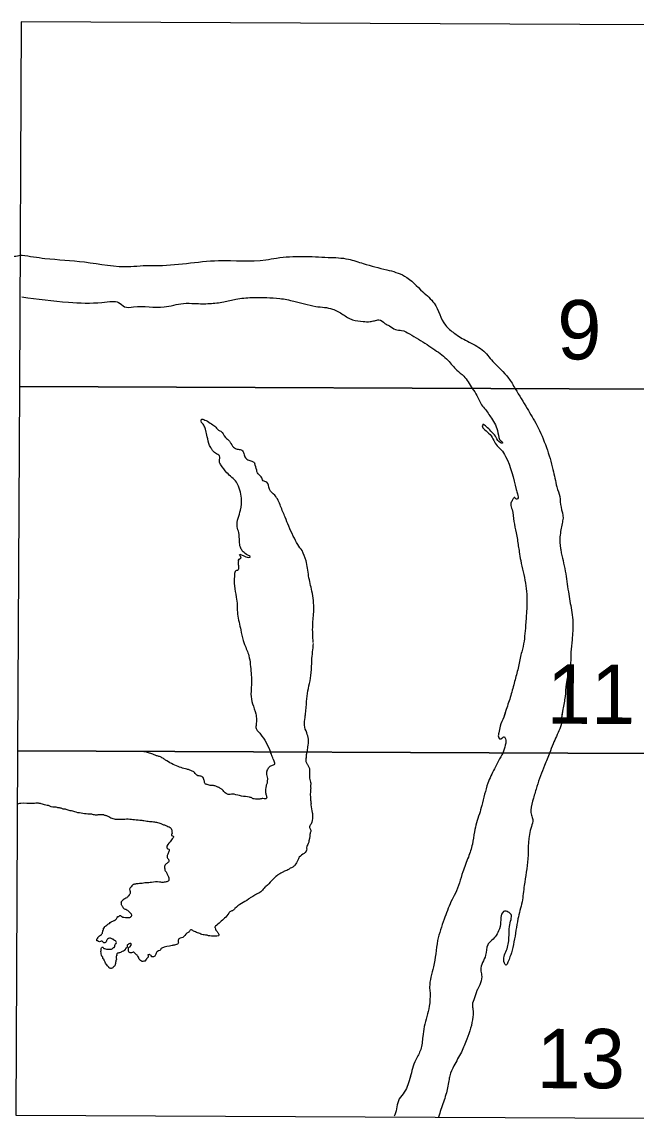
# Model space of a CAD drawing. Extents: x 3161564 to 3199464, y 849354 to 874788.
# Drawn here: x 3187465 to 3188676, y 851608 to 853769 of the extents above; entities that cross this region are included whole.
import ezdxf

# ---------------------------------------------------------------- set-up
doc = ezdxf.new("R2010")
doc.units = 0
doc.layers.add('V-ANNO-NPLT', color=7, linetype='Continuous')

msp = doc.modelspace()

# ---------------------------------------------------------------- linework, layer by layer
at = {"layer": 'V-ANNO-NPLT'}
for p, q in [((3188418, 852407.9), (3188415, 852398.6)), ((3188530.4, 852407.6), (3188529.1, 852396.2))]:
    msp.add_line(p, q, dxfattribs=at)
for points in [[(3187460.3, 853050.6), (3188699.2, 853044.8), (3188702.3, 853763.2), (3187464, 853769), (3187460.3, 853050.6)], [(3187456.7, 852332.3), (3188696.2, 852326.5), (3188699.2, 853044.8), (3187460.3, 853050.6), (3187456.7, 852332.3)], [(3187453, 851613.9), (3188693.2, 851608.1), (3188696.2, 852326.5), (3187456.7, 852332.3), (3187453, 851613.9)]]:
    msp.add_lwpolyline(points, dxfattribs=at)
for points in [[(3187329.4, 853339.6), (3187342.8, 853337.5), (3187357.1, 853333.9), (3187373.6, 853330.3), (3187388.4, 853326.6), (3187398.2, 853323), (3187410, 853319.9), (3187421.8, 853316.2), (3187431, 853312.6), (3187436.7, 853309.5), (3187442.8, 853306.9), (3187453.1, 853307.4), (3187465.5, 853309.5)], [(3187465.5, 853309.5), (3187510.7, 853302.9), (3187588.5, 853295.8), (3187680, 853286.9), (3187704.2, 853288.6), (3187726.7, 853288.5), (3187852.9, 853298.5), (3187946.2, 853300), (3187967, 853303.4), (3188018.8, 853306.7), (3188068.9, 853304.9), (3188108.7, 853301.3), (3188138, 853292.6), (3188184.6, 853280.3), (3188219.2, 853268.1), (3188255.4, 853236.9), (3188277.8, 853214.3), (3188300.1, 853171), (3188317.4, 853155.4), (3188343.2, 853139.7), (3188372.6, 853122.4), (3188393.3, 853099.8), (3188424.3, 853066.9), (3188437.6, 853045.8)], [(3187465.3, 853226.8), (3187557.1, 853216.3), (3187622.8, 853216.1), (3187643.5, 853217.8), (3187655.6, 853216), (3187667.7, 853207.4), (3187685, 853207.3), (3187745.5, 853207.1), (3187783.5, 853214), (3187806, 853213.9), (3187835.4, 853213.8), (3187863, 853217.2), (3187887.2, 853222.3), (3187918.3, 853225.7), (3187947.7, 853225.6), (3187973.6, 853223.8), (3188001.3, 853218.5), (3188022, 853213.3), (3188044.5, 853208), (3188061.7, 853206.3), (3188077.3, 853202.8), (3188098, 853192.3), (3188117, 853181.9), (3188137.7, 853178.4), (3188151.5, 853178.3), (3188160.2, 853180), (3188168.8, 853181.8), (3188180.9, 853174.8), (3188189.5, 853169.6), (3188201.6, 853162.6), (3188213.7, 853160.9), (3188229.2, 853153.9), (3188263.7, 853133), (3188279.3, 853122.6), (3188305.1, 853101.8), (3188322.3, 853082.7), (3188336.1, 853070.6), (3188352.6, 853046.6)], [(3188352.8, 853046.3), (3188362.2, 853032.4), (3188369.6, 853016.7), (3188377.1, 853007.1), (3188390.7, 852987.9), (3188403.6, 852959.2), (3188409.7, 852942.8), (3188411.8, 852941.4), (3188412.4, 852938.6), (3188408.3, 852939.3), (3188400.2, 852949.6), (3188392, 852959.9), (3188383.2, 852968.8), (3188377, 852974.3), (3188374.3, 852975.7), (3188373.6, 852975), (3188385.2, 852958.5), (3188400.1, 852935.9), (3188409.7, 852925.7), (3188418.5, 852912.6), (3188439.5, 852847)], [(3188437.6, 853045.9), (3188461.1, 853006.9), (3188480.1, 852974), (3188499.1, 852930.2), (3188512, 852886.4), (3188519.4, 852852.2)], [(3187827, 852966.3), (3187823.7, 852974), (3187818.5, 852981.8), (3187818.5, 852984.4), (3187819.8, 852985.7), (3187823.7, 852985), (3187828.2, 852983.1), (3187839.2, 852976.5), (3187847.6, 852970), (3187852.8, 852964.2), (3187857.3, 852962.2), (3187866.4, 852949.9), (3187874.1, 852942.7), (3187877.3, 852937.6), (3187884.4, 852929.1), (3187891.5, 852926.5), (3187898.7, 852924.5), (3187902.5, 852918), (3187903.8, 852913.5), (3187905.7, 852909.6), (3187912.8, 852905), (3187920, 852902.4), (3187922.5, 852901.1), (3187924.2, 852898.2)], [(3187857.5, 852895.8), (3187854.6, 852902), (3187855.2, 852908.4), (3187854.6, 852913.6), (3187846.8, 852918.8), (3187839.7, 852926.6), (3187835.2, 852933.8), (3187830.7, 852951.3), (3187827.5, 852963.6), (3187827, 852966.3)], [(3187891.9, 852705.8), (3187893.2, 852709.7), (3187897.1, 852712.2), (3187893.9, 852718.7), (3187906.8, 852714.8), (3187911.3, 852713.5), (3187915.2, 852714.1), (3187908.1, 852719.3), (3187899.7, 852726.5), (3187895.9, 852733.6), (3187894, 852745.3), (3187892.7, 852762.2), (3187889.5, 852773.8), (3187891.5, 852790.7), (3187896.1, 852806.2), (3187898.1, 852830.2), (3187894.9, 852845.8), (3187888.4, 852861.4), (3187869.1, 852880.2), (3187857.5, 852895.8)], [(3188017.6, 852726.8), (3188009.2, 852738.5), (3188000.2, 852755.4), (3187991.2, 852774.9), (3187984.1, 852792.4), (3187975.1, 852814.4), (3187963.5, 852835.9), (3187953.2, 852847.6), (3187948, 852861.8), (3187940.9, 852864.5), (3187937, 852872.2), (3187929.3, 852880), (3187928, 852885.2), (3187924.2, 852898.2)], [(3188519.4, 852852.2), (3188525.2, 852833.4), (3188527.8, 852812.2), (3188531.9, 852791), (3188529.8, 852780.1), (3188527.7, 852767.8), (3188525.6, 852754.1), (3188526.9, 852730.8), (3188528.3, 852722.6)], [(3188439.5, 852847), (3188441.9, 852838.4), (3188441.8, 852828.8), (3188439.8, 852828.2), (3188435.7, 852831.6), (3188435, 852830.9), (3188431.6, 852825.4), (3188428.8, 852818.6), (3188431.5, 852807.7), (3188434.9, 852784.4), (3188439.6, 852761.8), (3188443.6, 852735.9), (3188445.6, 852724.2)], [(3188039.4, 852545.9), (3188038.5, 852579.6), (3188040.6, 852609.4), (3188036.8, 852647), (3188030.4, 852676.9), (3188025.3, 852706.7), (3188017.6, 852726.8)], [(3188445.6, 852724.2), (3188448.3, 852707.1), (3188457.8, 852662.7), (3188460.4, 852640.8), (3188459.6, 852602.5), (3188457.5, 852573.8), (3188451.9, 852532.8), (3188448.5, 852521.2)], [(3188528.3, 852722.6), (3188537, 852680.9), (3188543.1, 852640.6), (3188549.1, 852605), (3188551.1, 852585.2), (3188549.6, 852551), (3188547.5, 852526.4)], [(3187891.9, 852706.4), (3187891.9, 852697.4), (3187891.9, 852690.9), (3187889.9, 852687.6), (3187886.7, 852687), (3187884.7, 852683.8), (3187884, 852676), (3187884, 852657.2), (3187887.8, 852635.1), (3187889.7, 852618.9), (3187889.7, 852611.2), (3187890.3, 852601.4), (3187896.7, 852570.3), (3187901.2, 852549.5), (3187904.1, 852541.6)], [(3187904.1, 852541.6), (3187912.4, 852519.6), (3187916.9, 852485.2), (3187918.1, 852469), (3187916.7, 852443.7), (3187919.9, 852424.9), (3187926.3, 852404.8), (3187927.6, 852393.8), (3187926.9, 852384), (3187926.9, 852376.3), (3187930.1, 852371.1), (3187935.3, 852365.2), (3187955.5, 852329.9)], [(3188027.4, 852329.6), (3188029.1, 852339.7), (3188029.8, 852355.2), (3188026.6, 852367.6), (3188022.1, 852382.5), (3188023.5, 852398), (3188026.1, 852424), (3188028.1, 852445.3), (3188032.1, 852464.8), (3188035.3, 852486.2), (3188036.7, 852510.1), (3188040, 852543.8)], [(3188448.5, 852521.2), (3188443.3, 852494.9), (3188436.4, 852468.9), (3188428.8, 852440.9), (3188419.9, 852413.6), (3188415, 852398.6)], [(3188547.5, 852526.4), (3188545.1, 852493.9), (3188538.1, 852463.8), (3188536, 852439.2), (3188531.2, 852414), (3188529.1, 852396.2)], [(3187924.9, 852409.3), (3187926.3, 852404.8), (3187927.6, 852393.8), (3187926.9, 852384), (3187926.9, 852376.3), (3187930.1, 852371.1), (3187935.3, 852365.2), (3187955.5, 852329.9)], [(3188027.4, 852329.6), (3188029.1, 852339.7), (3188029.8, 852355.2), (3188026.6, 852367.6), (3188022.1, 852382.5), (3188023.4, 852398), (3188024.6, 852409)], [(3188415, 852398.6), (3188407.8, 852380.5), (3188405.1, 852367.5), (3188404.3, 852360), (3188406.4, 852355.9), (3188412.5, 852357.9), (3188415.3, 852359.9), (3188418.7, 852355.8), (3188419.3, 852351), (3188418, 852343.5), (3188413.1, 852327.8)], [(3188415, 852398.6), (3188407.8, 852380.5), (3188405, 852367.5), (3188404.3, 852360), (3188406.4, 852355.8), (3188412.5, 852357.9), (3188415.3, 852359.9), (3188418.7, 852355.8), (3188419.3, 852351), (3188418, 852343.5), (3188413.1, 852327.8)], [(3188529.2, 852397), (3188528, 852383.5), (3188525.3, 852375.4), (3188512.2, 852346), (3188505.3, 852327.6)], [(3188529.2, 852397), (3188528, 852383.5), (3188525.3, 852375.3), (3188512.2, 852346), (3188505.3, 852327.5)], [(3187850.3, 852260.9), (3187844, 852263.4), (3187841.4, 852263.9), (3187838.3, 852263.8), (3187830.7, 852265.4), (3187828.3, 852266.1), (3187826.6, 852267.1), (3187824.9, 852272.1), (3187823.9, 852275.7), (3187822.5, 852279.3), (3187821.2, 852280.4), (3187818.2, 852282.1), (3187811.8, 852283), (3187805.4, 852289.3), (3187799.5, 852292.8), (3187793.4, 852295.1), (3187790.5, 852295.9), (3187784.7, 852297.3), (3187773.1, 852300.9), (3187760.1, 852307), (3187748.1, 852314), (3187742.7, 852317.7), (3187736.6, 852320.7), (3187730.4, 852322.5), (3187721.2, 852326.3), (3187712.6, 852328.9), (3187703, 852331), (3187702.7, 852331.1)], [(3188025.6, 852318.2), (3188024.6, 852314.2), (3188026, 852308.3), (3188029, 852303.9), (3188029.9, 852301.3), (3188031.2, 852298.9), (3188032.3, 852291.4), (3188032.2, 852280.7), (3188032.6, 852275.6), (3188034.7, 852265.7), (3188033.9, 852263), (3188034.3, 852260.6), (3188034.4, 852258), (3188033.9, 852255.4), (3188034.3, 852252.7), (3188033.2, 852247.3), (3188034.1, 852242.1), (3188033.8, 852239.5), (3188033.9, 852236.7), (3188035.1, 852228.4), (3188034.9, 852225.7), (3188037.6, 852210.2), (3188037.7, 852202.3), (3188035.4, 852188), (3188033.5, 852185.6), (3188032.1, 852182.5), (3188034, 852177.3), (3188034.6, 852174.6), (3188034.3, 852171.8), (3188033.1, 852168.8), (3188032.5, 852166), (3188032.6, 852163.2), (3188032.2, 852160.4), (3188031.5, 852157.6), (3188031.1, 852155), (3188029.6, 852149.6), (3188026.3, 852141.2), (3188026.6, 852138.8), (3188012, 852122.2), (3188010.2, 852119.4), (3188009, 852116.3), (3188003.2, 852106.8), (3187999, 852102.9), (3187994.1, 852100.5), (3187991.9, 852098.8), (3187987.2, 852096.4), (3187983, 852095), (3187980.6, 852093.4), (3187978.1, 852092.2), (3187973.5, 852089.7), (3187968.7, 852086.5), (3187946.3, 852064.9), (3187944.2, 852063.1), (3187938, 852055.9), (3187930.2, 852050.7), (3187925.6, 852048.3), (3187918.8, 852044), (3187913.9, 852041.3), (3187911.6, 852039.5), (3187885.1, 852021.2), (3187880.7, 852017), (3187877.8, 852016.1), (3187875, 852014.6), (3187873.1, 852012.1), (3187864.6, 852002), (3187846.8, 851986.4), (3187845.5, 851984.5), (3187845.9, 851983), (3187847.8, 851978.3), (3187851.6, 851973.7), (3187852.6, 851971.4), (3187854.2, 851969.2), (3187852.5, 851967.6), (3187846.9, 851966.7), (3187838.7, 851966.8), (3187833.2, 851967.6), (3187830.2, 851968.4), (3187827.3, 851969), (3187822.2, 851969.5), (3187813.7, 851972.9), (3187805.3, 851975.9), (3187802.3, 851977.8), (3187799.5, 851979.1), (3187797, 851978.6), (3187795.1, 851975.9), (3187793, 851974), (3187790.6, 851972.5), (3187782.2, 851964.3), (3187777.2, 851963), (3187773.3, 851958.5), (3187773, 851955.8), (3187773.6, 851953.5), (3187771.6, 851950.9), (3187764.2, 851948.8), (3187761.6, 851948.2), (3187741, 851943), (3187738.9, 851941.5)], [(3187948.7, 852293.2), (3187952.7, 852300.1), (3187954.7, 852301.9), (3187961, 852304.4), (3187963.5, 852306), (3187961.5, 852313.6), (3187960.8, 852315.9), (3187958.6, 852320.8), (3187955.5, 852329.9)], [(3188025.6, 852318.2), (3188026.1, 852320.8), (3188026.2, 852323.4), (3188027.4, 852329.6)], [(3188413.1, 852327.8), (3188396.5, 852296.6), (3188383.7, 852268.2), (3188371.8, 852224.3), (3188366.9, 852207.6), (3188357, 852172.5), (3188353.1, 852148), (3188345.2, 852122.6), (3188334.4, 852093.3), (3188319.6, 852051.3), (3188310.7, 852034.7)], [(3188505.7, 852328.6), (3188495.1, 852303.1), (3188480.4, 852262.1), (3188473.5, 852238.6), (3188468.5, 852215.2), (3188469.5, 852205.4), (3188472.4, 852196.6), (3188469.4, 852182.9), (3188462.4, 852119.4), (3188455.4, 852066.6), (3188451.4, 852034.3)], [(3187948.7, 852293.3), (3187947.3, 852290.3), (3187947.4, 852285.2), (3187949.1, 852275.2), (3187948.8, 852272.6), (3187948.9, 852270.1), (3187946.6, 852264.4), (3187946.5, 852261.9), (3187946, 852259.1), (3187945.3, 852253.8), (3187946.3, 852246.4), (3187947.9, 852239.9), (3187947.9, 852239.3), (3187947, 852238), (3187945.6, 852237.4), (3187940.3, 852238), (3187937.2, 852237.5), (3187935.8, 852237.2), (3187928, 852236.8), (3187922.9, 852237.2), (3187916.8, 852239.8), (3187914.1, 852240.6), (3187897.9, 852242.9), (3187883.5, 852246.4), (3187878.3, 852246.7), (3187873.3, 852246), (3187870.5, 852246.6), (3187867.7, 852248), (3187861.9, 852253.6), (3187861.4, 852254.5), (3187858.9, 852256.4), (3187854.2, 852259.5), (3187851.9, 852260.6), (3187850.3, 852260.9)], [(3187626.8, 852205.7), (3187623.7, 852205.9), (3187615.2, 852205.7), (3187612.6, 852205.5), (3187604.3, 852206.7), (3187601.5, 852207.5), (3187598.9, 852207.3), (3187585.3, 852208.8), (3187572, 852211), (3187563.2, 852213.8), (3187560.6, 852213.8), (3187552.2, 852216.7), (3187549.5, 852217), (3187543.9, 852218.2), (3187540.9, 852219.3), (3187538, 852219.6), (3187531.4, 852221.1), (3187528.8, 852220.9), (3187517.6, 852224), (3187512.1, 852225.1), (3187503.5, 852227.8), (3187500.6, 852228.3), (3187497.9, 852228.6), (3187492.5, 852228.6), (3187487.2, 852228.1), (3187463.1, 852228.5), (3187460.5, 852228.1), (3187456.1, 852226.9)], [(3187626.8, 852205.7), (3187629.5, 852205.3), (3187632.2, 852204.4), (3187640.8, 852200.2), (3187648.9, 852197.7), (3187664.9, 852197.4), (3187678.2, 852197.6), (3187683.8, 852196.8), (3187697.5, 852195.7), (3187705.8, 852194.5), (3187711.5, 852193.6), (3187722.3, 852192.6), (3187730.4, 852191.4), (3187739.1, 852188.9), (3187744.6, 852186.4), (3187747.6, 852185.5), (3187750.6, 852184.2), (3187759.3, 852178.9), (3187761, 852171.8), (3187761.1, 852169.2), (3187760, 852166.4), (3187760.4, 852165.4), (3187763.4, 852164), (3187764.2, 852162.6), (3187763.2, 852160.9), (3187757.3, 852152.7), (3187751, 852141.1), (3187751.8, 852139.4), (3187754.7, 852138.3), (3187755.6, 852137.2), (3187755.6, 852135.1), (3187753, 852128.7), (3187751.8, 852125.6), (3187751.4, 852122.9), (3187752.4, 852120.5), (3187754.3, 852118.1), (3187755, 852115.7), (3187753.9, 852112.9), (3187751.8, 852110.7), (3187749.4, 852109.1), (3187747.3, 852107.1), (3187746.6, 852104.4), (3187746.6, 852101.7), (3187747.2, 852096.9), (3187750.1, 852092.4), (3187751.2, 852090), (3187753.3, 852085.3), (3187755.1, 852077.8), (3187754.8, 852076.2), (3187753.3, 852075), (3187751.2, 852074.1), (3187743.9, 852072.8), (3187738.8, 852073), (3187736.2, 852073.5), (3187720.5, 852072.8), (3187715.4, 852072), (3187704.8, 852071.3), (3187699.7, 852070.4), (3187694.6, 852070.2), (3187686.9, 852069.1), (3187684.4, 852068.5), (3187683.6, 852067.9), (3187680.8, 852064.1), (3187678.8, 852062), (3187677.6, 852059.2), (3187678.6, 852054.7), (3187678.8, 852052.2), (3187677.7, 852049.4), (3187675.9, 852046.5), (3187673.9, 852044.3), (3187671.8, 852042.6), (3187665, 852038.6), (3187661.7, 852034.9)], [(3187647.7, 851945.9), (3187648.4, 851946.6), (3187648.9, 851950.4), (3187651.1, 851952.4), (3187650.5, 851956.6), (3187649.8, 851957.4), (3187646.1, 851959.6), (3187644.8, 851960.9), (3187643.5, 851961.1), (3187641.1, 851962.4), (3187638.2, 851962.8), (3187633.8, 851961), (3187632.6, 851958.9), (3187631.9, 851957.6), (3187630.3, 851954.3), (3187626.9, 851953.5), (3187624.8, 851955.5), (3187621.7, 851957.1), (3187618, 851955.9), (3187616.1, 851956.5), (3187614.6, 851957.4), (3187613.8, 851957.5), (3187613.1, 851957.7), (3187612.8, 851960), (3187613.1, 851961.2), (3187614.3, 851962.3), (3187615, 851963.9), (3187621.9, 851970), (3187624.5, 851976), (3187624.5, 851977), (3187625.8, 851978.9), (3187626, 851981.2), (3187626.9, 851983.2), (3187627.8, 851983.4), (3187627.7, 851984), (3187628.9, 851985.6), (3187630.9, 851986.9), (3187634.5, 851990.5), (3187637.7, 851992), (3187641.1, 851994.9), (3187647.6, 851997.8), (3187648.4, 851998.2), (3187650, 851999.1), (3187650.2, 851999.7), (3187651.7, 852001), (3187654.2, 852005.2), (3187656, 852005.8), (3187657.4, 852006.7), (3187659.6, 852007.2), (3187662.2, 852005.3), (3187666, 852004), (3187672.6, 852003.3), (3187676.6, 852003.6), (3187679, 852004.2), (3187680.5, 852005.2), (3187680.7, 852006.2), (3187681.3, 852006.4), (3187681.6, 852008.4), (3187681.3, 852010), (3187680.2, 852011.1), (3187676.6, 852014.9), (3187670.5, 852019), (3187669.5, 852019.3), (3187663.9, 852024.4), (3187663.4, 852025.5), (3187662.1, 852027.4), (3187661.5, 852030), (3187661.2, 852033.2), (3187661.7, 852034.9)], [(3188310.7, 852034.7), (3188297.5, 852000), (3188284.7, 851958), (3188276.7, 851906.2), (3188268.8, 851866.1), (3188269.7, 851855.4)], [(3188451.4, 852034.3), (3188443, 852000.6), (3188435.1, 851955.6), (3188430.1, 851934.1), (3188423.3, 851915.6), (3188419.3, 851909.7), (3188416.4, 851913.6), (3188420.4, 851939.1), (3188425.3, 851963.5), (3188426.4, 851986), (3188429.3, 851999.7), (3188429.4, 852009.4), (3188423.5, 852014.3), (3188416.7, 852016.3), (3188409.8, 852006.6), (3188408.8, 851994.8), (3188404.9, 851977.2), (3188398, 851965.5), (3188389.2, 851956.7), (3188383.3, 851949.9), (3188379.3, 851929.4), (3188369.5, 851900.1), (3188371.4, 851890.3), (3188361.6, 851859)], [(3187713.3, 851929.7), (3187714, 851925.4), (3187712.5, 851923.8), (3187712.1, 851923.2), (3187710.6, 851922.1), (3187710.5, 851921.3), (3187708.5, 851918.3), (3187708.6, 851918), (3187707.3, 851917.6), (3187700.9, 851917.2), (3187697.6, 851920.3), (3187695.9, 851923.1), (3187694, 851927.2), (3187690.3, 851930.9), (3187688.6, 851932.8), (3187686, 851934.9), (3187679.9, 851933.8), (3187678.4, 851934.1), (3187676.7, 851935), (3187676, 851935.7), (3187675.3, 851938.7), (3187675.9, 851944.3), (3187677.3, 851945.5), (3187678.2, 851945.8), (3187678.4, 851946.4), (3187679, 851946.7), (3187679.3, 851947.7), (3187680.1, 851948.2), (3187680.1, 851952.2), (3187679.5, 851952.3), (3187676.1, 851951.4), (3187675.5, 851951), (3187673.3, 851949.9), (3187672.7, 851948.3), (3187672.9, 851947.1), (3187672.5, 851946.5), (3187672.6, 851945.5), (3187672.2, 851944.1), (3187671.4, 851943.8), (3187671.4, 851943.2), (3187670.4, 851942.8), (3187668.6, 851940.7), (3187668.3, 851939.6), (3187667.6, 851939.2), (3187667.2, 851938.4), (3187662.9, 851936.6), (3187660.7, 851935.2), (3187654.7, 851933.3), (3187653.8, 851933), (3187652.6, 851931.9), (3187652, 851929.8), (3187652.1, 851928.7), (3187650.8, 851926.8), (3187651.5, 851920.6), (3187650.8, 851920), (3187650.4, 851916.4), (3187649.5, 851914.8), (3187649.7, 851912.5), (3187649.1, 851911.8), (3187649.3, 851910.4), (3187648.5, 851908.5), (3187647.4, 851907.4), (3187645.5, 851906.1), (3187644.9, 851905.5), (3187643.4, 851903.9), (3187641.5, 851903.3), (3187639.3, 851903.5), (3187636.8, 851904.8), (3187635.9, 851906), (3187634.3, 851907.3), (3187633.8, 851908.3), (3187629.3, 851915.4), (3187628.2, 851918), (3187627.6, 851918.5), (3187626.4, 851921.1), (3187625.8, 851921.3), (3187624.9, 851922.8), (3187623.7, 851926.9), (3187623, 851927.6), (3187621, 851936.5), (3187620.9, 851937.2), (3187621.5, 851938.5), (3187621.4, 851940.8), (3187622, 851943.8), (3187623.3, 851944.8), (3187625, 851945.1), (3187626.1, 851942.9), (3187627.1, 851942.4), (3187628.2, 851942.3), (3187632.3, 851941), (3187636.2, 851941.2), (3187636.7, 851941), (3187639.5, 851941), (3187643.3, 851941.9), (3187645.8, 851944.2), (3187647.7, 851945.1), (3187647.7, 851945.9)], [(3187738.9, 851941.5), (3187737.2, 851938.7), (3187732.2, 851936.7), (3187730.3, 851934.4), (3187729.1, 851931.5), (3187727.9, 851928.7), (3187725.8, 851926.6), (3187723.5, 851925.9), (3187720.9, 851926.2), (3187720, 851928.4), (3187717.2, 851930.2), (3187716.3, 851930.4), (3187713.3, 851929.7)], [(3188362.2, 851861.1), (3188357.1, 851844.9), (3188353.2, 851831.2), (3188354.1, 851822.4), (3188354.1, 851807.7), (3188342.2, 851763.7), (3188331.4, 851738.3), (3188316.7, 851711), (3188308.8, 851691.5), (3188306.8, 851681.7)], [(3188269.7, 851855.4), (3188268.2, 851828.5), (3188258.3, 851788.4), (3188255.3, 851768.9), (3188251.3, 851743.4), (3188241.5, 851722.9), (3188230.7, 851688.7)], [(3188231, 851689.9), (3188218.9, 851659.4), (3188209.1, 851645.8), (3188200.2, 851614.5), (3188199.2, 851612.2)], [(3188306.8, 851681.7), (3188300.9, 851654.3), (3188291.1, 851625), (3188286.5, 851610.1)]]:
    msp.add_spline(points, degree=3, dxfattribs=at)

# ---------------------------------------------------------------- texts
for s, p in [('9', (3188520.2, 853103.8)), ('11', (3188499.7, 852385.5)), ('13', (3188479.6, 851667.2))]:
    msp.add_text(s, height=117, rotation=359.8417, dxfattribs=at).set_placement(p)

doc.saveas('drawing.dxf')
